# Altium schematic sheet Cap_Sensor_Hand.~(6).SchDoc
size A3
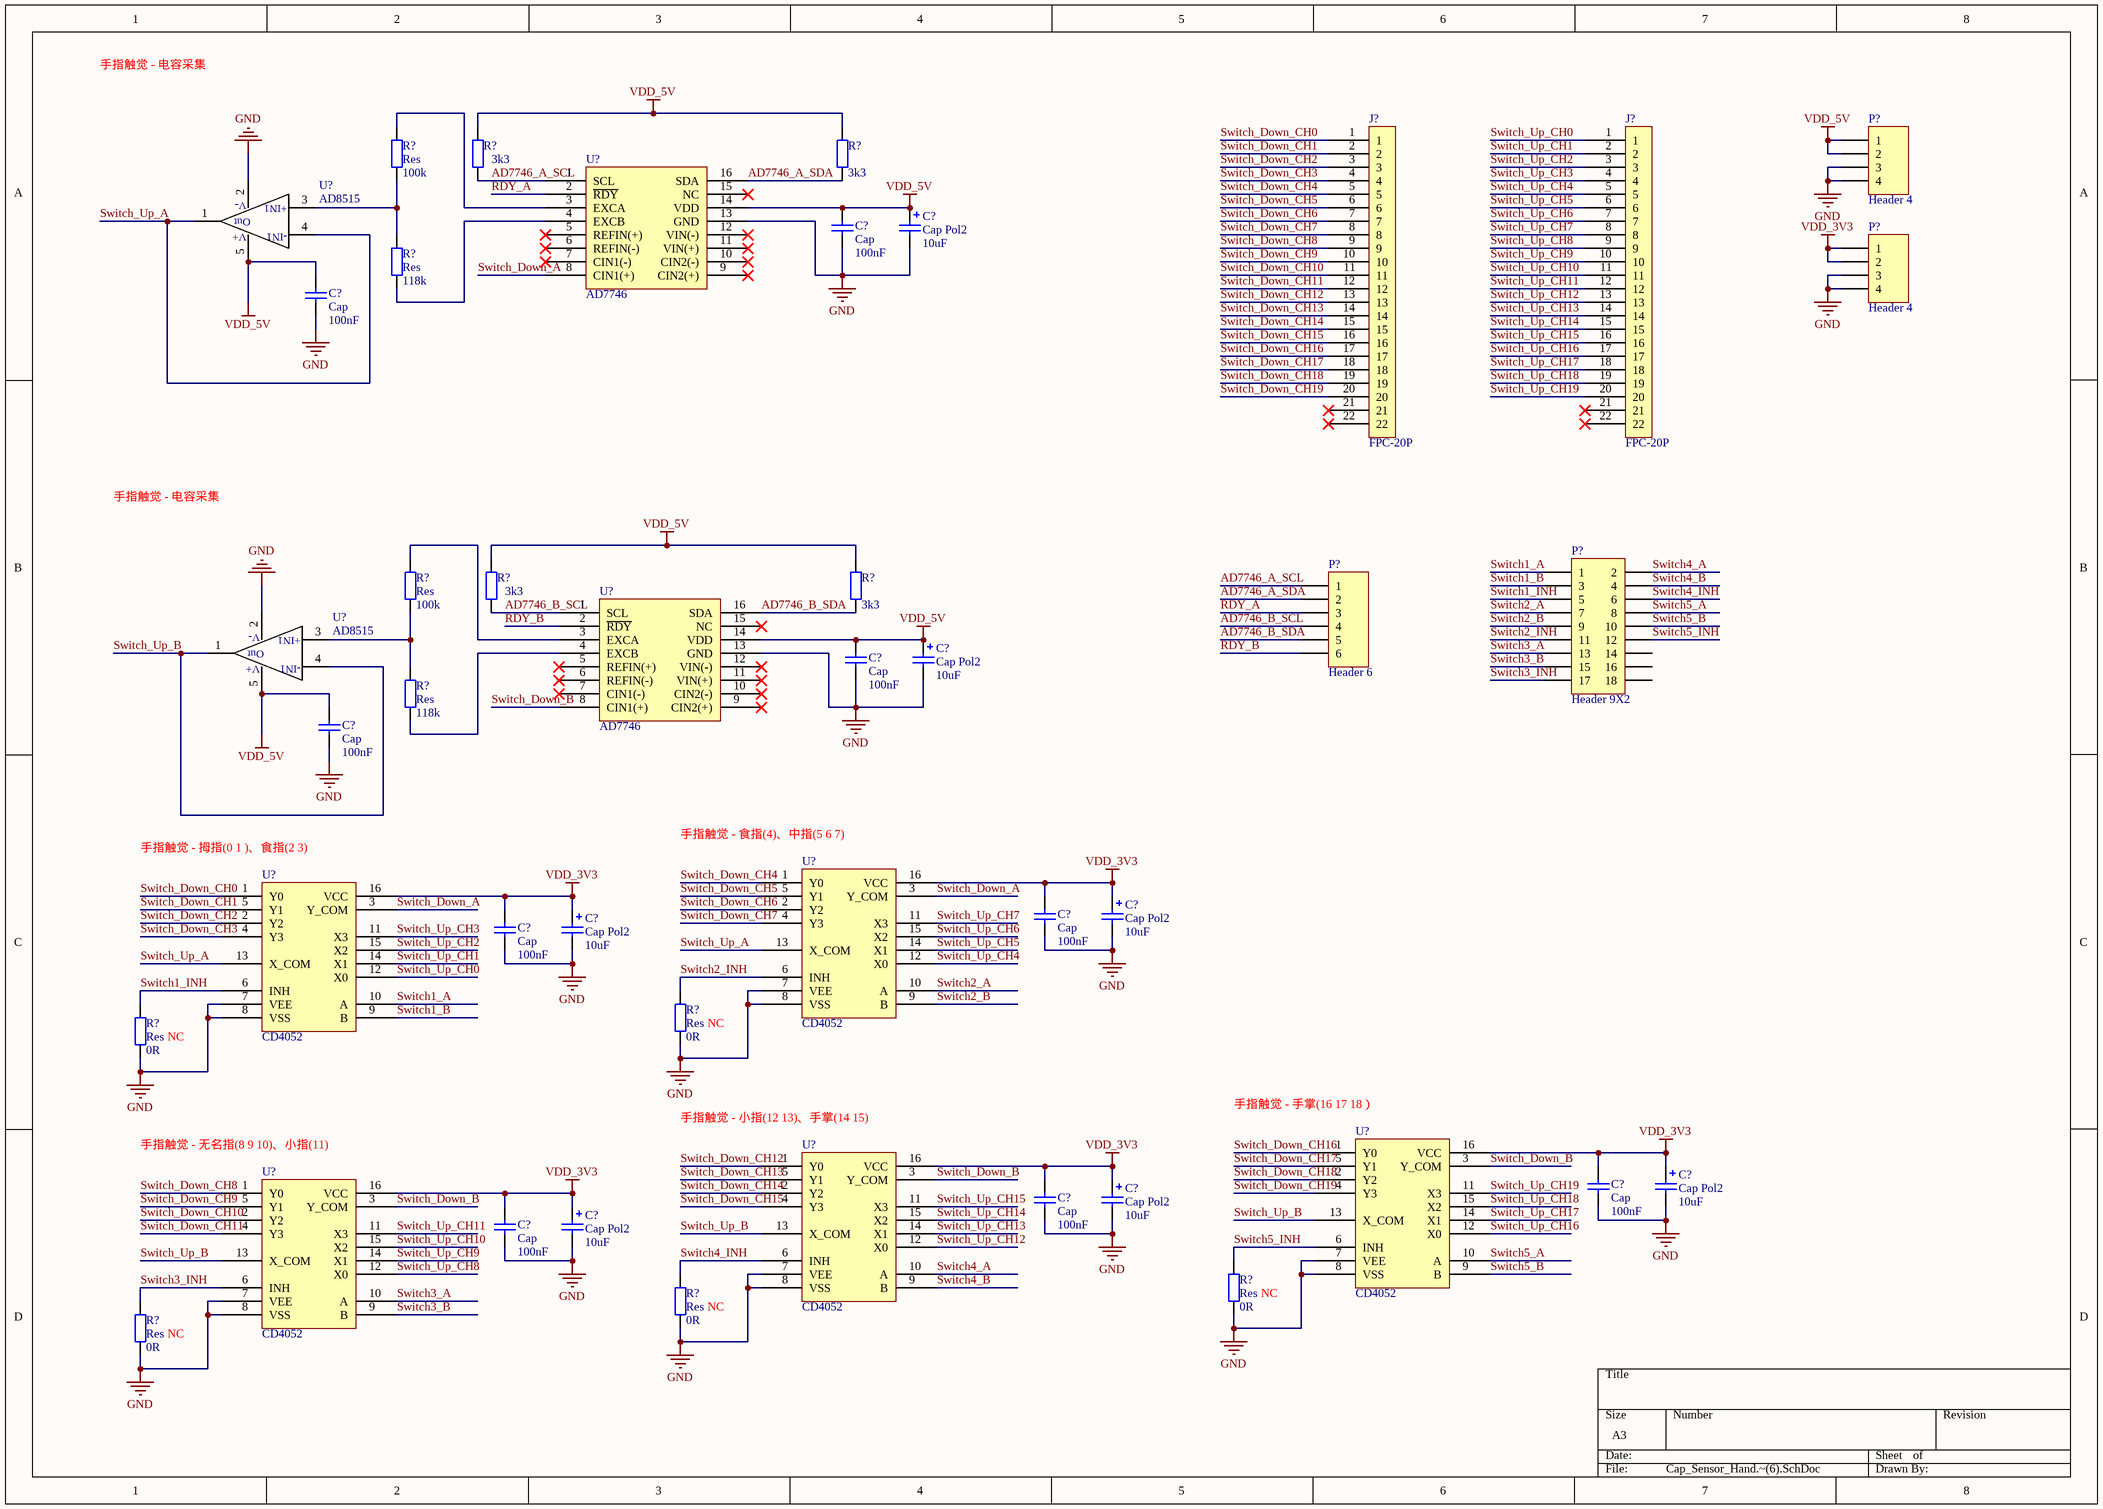
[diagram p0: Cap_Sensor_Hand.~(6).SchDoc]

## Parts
(Parts that share a designator on the sheet are numbered #1, #2 ... from top to bottom, then left to right.)
C?#1  Cap Pol2  value 10uF  [Cap-TA]
C?#2  Cap  value 100nF  [0805C]
C?#3  Cap  value 100nF  [0805C]
C?#4  Cap Pol2  value 10uF  [Cap-TA]
C?#5  Cap  value 100nF  [0805C]
C?#6  Cap  value 100nF  [0805C]
C?#7  Cap Pol2  value 10uF  [Cap-TA]
C?#8  Cap Pol2  value 10uF  [Cap-TA]
C?#9  Cap  value 100nF  [0805C]
C?#10  Cap  value 100nF  [0805C]
C?#11  Cap Pol2  value 10uF  [Cap-TA]
C?#12  Cap Pol2  value 10uF  [Cap-TA]
C?#13  Cap  value 100nF  [0805C]
C?#14  Cap  value 100nF  [0805C]
C?#15  Cap Pol2  value 10uF  [Cap-TA]
C?#16  Cap  value 100nF  [0805C]
J?#1  FPC-20P  [FPC20-0.5]
J?#2  FPC-20P  [FPC20-0.5]
P?#1  Header 4  [HDR1X4]
P?#2  Header 4  [HDR1X4]
P?#3  Header 9X2  [HDR2X9]
P?#4  Header 6  [HDR1X6]
R?#1  Res  value 100k  [0805R]
R?#2  value 3k3  [0805R]  (hidden comment: Res)
R?#3  value 3k3  [0805R]  (hidden comment: Res)
R?#4  Res  value 118k  [0805R]
R?#5  Res  value 100k  [0805R]
R?#6  value 3k3  [0805R]  (hidden comment: Res)
R?#7  value 3k3  [0805R]  (hidden comment: Res)
R?#8  Res  value 118k  [0805R]
R?#9  Res  value 0R  [0805R]
R?#10  Res  value 0R  [0805R]
R?#11  Res  value 0R  [0805R]
R?#12  Res  value 0R  [0805R]
R?#13  Res  value 0R  [0805R]
U?#1  AD8515  [sot23-5]
U?#2  AD7746  [TSSOP16]
U?#3  AD8515  [sot23-5]
U?#4  AD7746  [TSSOP16]
U?#5  CD4052  [sop16]
U?#6  CD4052  [SOP16]
U?#7  CD4052  [sop16]
U?#8  CD4052  [sop16]
U?#9  CD4052  [sop16]

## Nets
GND: C?#1.2 C?#2.1 C?#3.1 C?#4.2 C?#5.1 C?#6.1 C?#7.2 C?#8.2 C?#9.1 C?#10.1 C?#11.2 C?#12.2 C?#13.1 C?#14.1 C?#15.2 C?#16.1 P?#1.3 P?#1.4 P?#2.3 P?#2.4 R?#9.2 R?#10.2 R?#11.2 R?#12.2 R?#13.2 U?#1.2(V-) U?#2.13(GND) U?#3.2(V-) U?#4.13(GND) U?#5.7(VEE) U?#5.8(VSS) U?#6.7(VEE) U?#6.8(VSS) U?#7.7(VEE) U?#7.8(VSS) U?#8.7(VEE) U?#8.8(VSS) U?#9.7(VEE) U?#9.8(VSS)
VDD_3V3: C?#7.1 C?#8.1 C?#9.2 C?#10.2 C?#11.1 C?#12.1 C?#13.2 C?#14.2 C?#15.1 C?#16.2 P?#2.1 P?#2.2 U?#5.16(VCC) U?#6.16(VCC) U?#7.16(VCC) U?#8.16(VCC) U?#9.16(VCC)
VDD_5V: C?#1.1 C?#2.2 C?#3.2 C?#4.1 C?#5.2 C?#6.2 P?#1.1 P?#1.2 R?#2.2 R?#3.2 R?#6.2 R?#7.2 U?#1.5(V+) U?#2.14(VDD) U?#3.5(V+) U?#4.14(VDD)
AD7746_A_SCL: P?#4.1 R?#2.1 U?#2.1(SCL)
AD7746_A_SDA: P?#4.2 R?#3.1 U?#2.16(SDA)
AD7746_B_SCL: P?#4.4 R?#6.1 U?#4.1(SCL)
AD7746_B_SDA: P?#4.5 R?#7.1 U?#4.16(SDA)
RDY_A: P?#4.3 U?#2.2(~{RDY})
RDY_B: P?#4.6 U?#4.2(~{RDY})
Switch1_A: P?#3.1 U?#6.10(A)
Switch1_B: P?#3.3 U?#6.9(B)
Switch1_INH: P?#3.5 R?#10.1 U?#6.6(INH)
Switch2_A: P?#3.7 U?#5.10(A)
Switch2_B: P?#3.9 U?#5.9(B)
Switch2_INH: P?#3.11 R?#9.1 U?#5.6(INH)
Switch3_A: P?#3.13 U?#9.10(A)
Switch3_B: P?#3.15 U?#9.9(B)
Switch3_INH: P?#3.17 R?#13.1 U?#9.6(INH)
Switch4_A: P?#3.2 U?#8.10(A)
Switch4_B: P?#3.4 U?#8.9(B)
Switch4_INH: P?#3.6 R?#12.1 U?#8.6(INH)
Switch5_A: P?#3.8 U?#7.10(A)
Switch5_B: P?#3.10 U?#7.9(B)
Switch5_INH: P?#3.12 R?#11.1 U?#7.6(INH)
Switch_Down_A: U?#2.8(CIN1(+)) U?#5.3(Y_COM) U?#6.3(Y_COM)
Switch_Down_B: U?#4.8(CIN1(+)) U?#7.3(Y_COM) U?#8.3(Y_COM) U?#9.3(Y_COM)
Switch_Down_CH0: J?#1.1 U?#6.1(Y0)
Switch_Down_CH1: J?#1.2 U?#6.5(Y1)
Switch_Down_CH2: J?#1.3 U?#6.2(Y2)
Switch_Down_CH3: J?#1.4 U?#6.4(Y3)
Switch_Down_CH4: J?#1.5 U?#5.1(Y0)
Switch_Down_CH5: J?#1.6 U?#5.5(Y1)
Switch_Down_CH6: J?#1.7 U?#5.2(Y2)
Switch_Down_CH7: J?#1.8 U?#5.4(Y3)
Switch_Down_CH8: J?#1.9 U?#9.1(Y0)
Switch_Down_CH9: J?#1.10 U?#9.5(Y1)
Switch_Down_CH10: J?#1.11 U?#9.2(Y2)
Switch_Down_CH11: J?#1.12 U?#9.4(Y3)
Switch_Down_CH12: J?#1.13 U?#8.1(Y0)
Switch_Down_CH13: J?#1.14 U?#8.5(Y1)
Switch_Down_CH14: J?#1.15 U?#8.2(Y2)
Switch_Down_CH15: J?#1.16 U?#8.4(Y3)
Switch_Down_CH16: J?#1.17 U?#7.1(Y0)
Switch_Down_CH17: J?#1.18 U?#7.5(Y1)
Switch_Down_CH18: J?#1.19 U?#7.2(Y2)
Switch_Down_CH19: J?#1.20 U?#7.4(Y3)
Switch_Up_A: U?#1.1(Out1) U?#1.4(-IN) U?#5.13(X_COM) U?#6.13(X_COM)
Switch_Up_B: U?#3.1(Out1) U?#3.4(-IN) U?#7.13(X_COM) U?#8.13(X_COM) U?#9.13(X_COM)
Switch_Up_CH0: J?#2.1 U?#6.12(X0)
Switch_Up_CH1: J?#2.2 U?#6.14(X1)
Switch_Up_CH2: J?#2.3 U?#6.15(X2)
Switch_Up_CH3: J?#2.4 U?#6.11(X3)
Switch_Up_CH4: J?#2.5 U?#5.12(X0)
Switch_Up_CH5: J?#2.6 U?#5.14(X1)
Switch_Up_CH6: J?#2.7 U?#5.15(X2)
Switch_Up_CH7: J?#2.8 U?#5.11(X3)
Switch_Up_CH8: J?#2.9 U?#9.12(X0)
Switch_Up_CH9: J?#2.10 U?#9.14(X1)
Switch_Up_CH10: J?#2.11 U?#9.15(X2)
Switch_Up_CH11: J?#2.12 U?#9.11(X3)
Switch_Up_CH12: J?#2.13 U?#8.12(X0)
Switch_Up_CH13: J?#2.14 U?#8.14(X1)
Switch_Up_CH14: J?#2.15 U?#8.15(X2)
Switch_Up_CH15: J?#2.16 U?#8.11(X3)
Switch_Up_CH16: J?#2.17 U?#7.12(X0)
Switch_Up_CH17: J?#2.18 U?#7.14(X1)
Switch_Up_CH18: J?#2.19 U?#7.15(X2)
Switch_Up_CH19: J?#2.20 U?#7.11(X3)
NetR?#1_1: R?#1.1 U?#2.3(EXCA)
NetR?#1_2: R?#1.2 R?#4.1 U?#1.3(+IN)
NetR?#4_2: R?#4.2 U?#2.4(EXCB)
NetR?#5_1: R?#5.1 U?#4.3(EXCA)
NetR?#5_2: R?#5.2 R?#8.1 U?#3.3(+IN)
NetR?#8_2: R?#8.2 U?#4.4(EXCB)

Not connected (* = marked no-connect by the designer): J?#1 21* 22*; J?#2 21* 22*; P?#3 14 16 18; U?#2 5(REFIN(+))* 6(REFIN(-))* 7(CIN1(-))* 9(CIN2(+))* 10(CIN2(-))* 11(VIN(+))* 12(VIN(-))* 15(NC)*; U?#4 5(REFIN(+))* 6(REFIN(-))* 7(CIN1(-))* 9(CIN2(+))* 10(CIN2(-))* 11(VIN(+))* 12(VIN(-))* 15(NC)*

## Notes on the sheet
- 手指触觉 - 电容采集
- (near U?#6) 手指触觉 - 拇指(0 1 )、食指(2 3)
- (near U?#5) 手指触觉 - 食指(4)、中指(5 6 7)
- (near R?#10) NC
- (near R?#9) NC
- (near U?#8) 手指触觉 - 小指(12 13)、手掌(14 15)
- (near U?#7) 手指触觉 - 手掌(16 17 18）
- (near U?#9) 手指触觉 - 无名指(8 9 10)、小指(11)
- (near R?#12) NC
- (near R?#11) NC
- (near R?#13) NC

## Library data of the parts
C?#1 C?#4 C?#7 C?#8 C?#11 C?#12 C?#15 = Cap Pol2: Polarized Capacitor (Axial)
C?#2 C?#3 C?#5 C?#6 C?#9 C?#10 C?#13 C?#14 C?#16 = Cap: Capacitor
J?#1 J?#2 = FPC_20P
P?#1 P?#2 = Header 4: Header, 4-Pin
P?#3 = Header 9X2: Header, 9-Pin, Dual row
P?#4 = Header 6: Header, 6-Pin
R?#1-R?#13 = Res: Resistor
